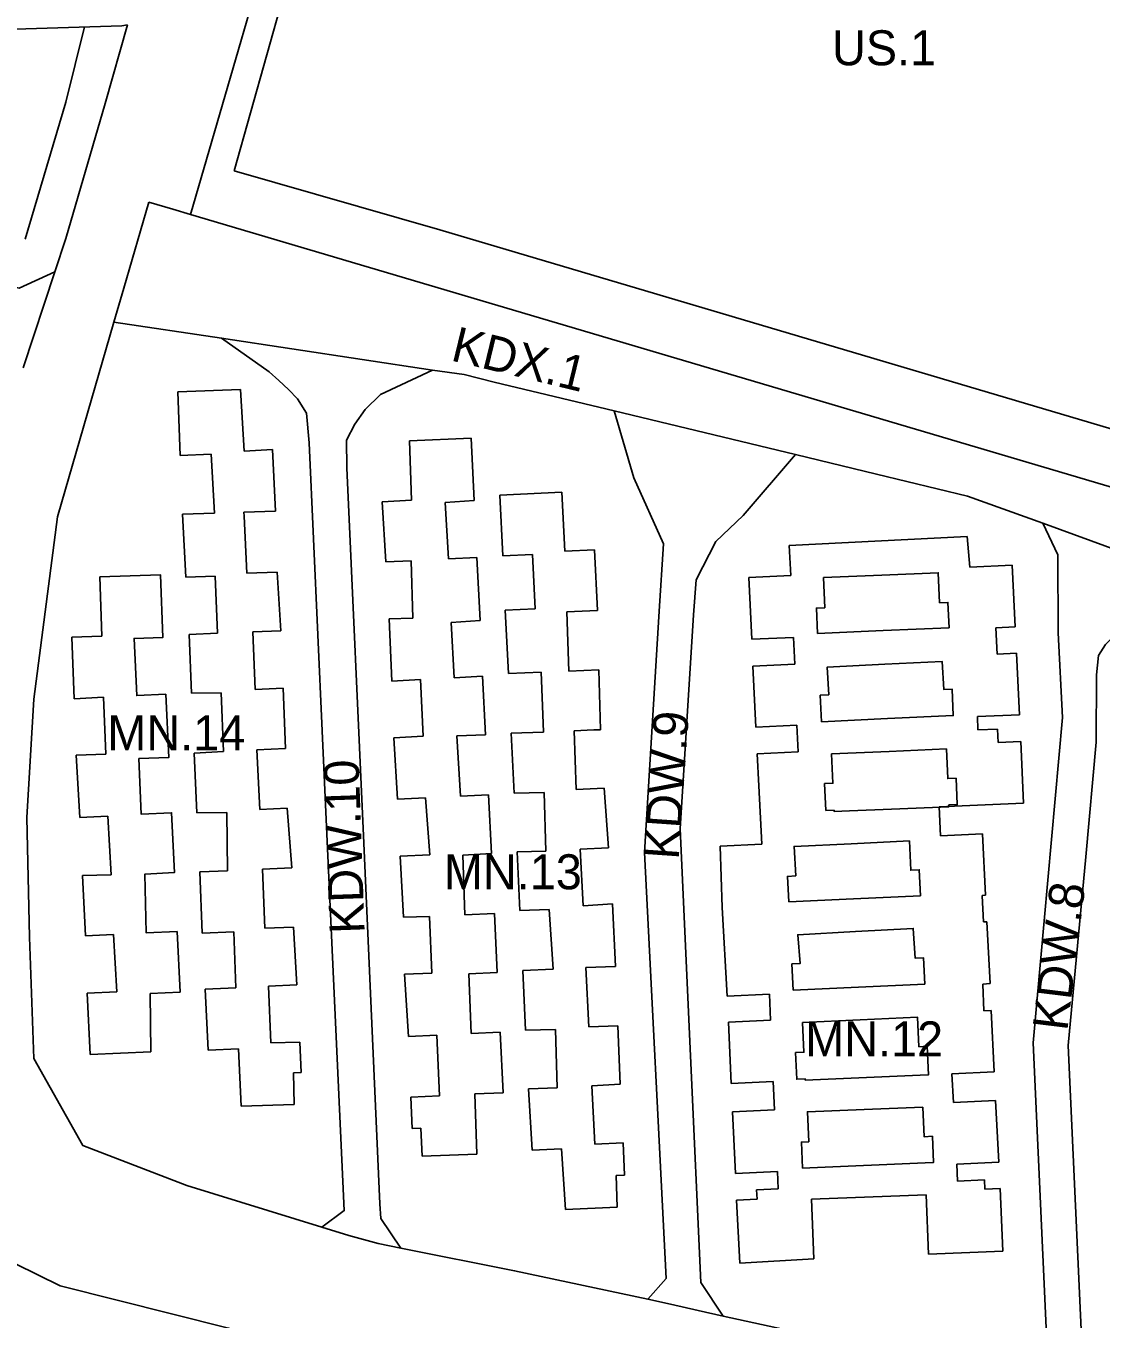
# Model space of a CAD drawing. Extents: x 7419601 to 7420547, y 5548907 to 5549873.
# Drawn here: x 7419879.6 to 7420033.1, y 5549211.8 to 5549396.6 of the extents above; entities that cross this region are included whole.
import ezdxf

# ---------------------------------------------------------------- set-up
doc = ezdxf.new("R2010")
doc.units = 0
for name, color, linetype in [('LIN_linie_rozgraniczajace', 7, 'Continuous'), ('LIN_nieprzekraczalna linia zabudowy', 7, 'Continuous'), ('LIN_obowiązująca linia zabudowy', 7, 'Continuous'), ('TXT_opisy_przeznaczen', 7, 'Continuous')]:
    doc.layers.add(name, color=color, linetype=linetype)

msp = doc.modelspace()

# ---------------------------------------------------------------- linework, layer by layer
at = {"layer": 'LIN_linie_rozgraniczajace'}
for p, q in [((7419879.24, 5549347.7), (7419883.76, 5549361.41)), ((7419907.57, 5549351.94), (7419937.7, 5549347.35)), ((7419963.61, 5549341.58), (7419989.53, 5549335.34)), ((7419925.75, 5549223.74), (7419929.9, 5549222.61)), ((7419971.65, 5549213.96), (7419975.63, 5549213.02))]:
    msp.add_line(p, q, dxfattribs=at)
for points in [[(7419903.11, 5549369.61), (7419918, 5549420.91), (7419915.74, 5549421.56), (7419928.75, 5549463.85), (7419929.6, 5549464.8), (7419930.22, 5549465.38), (7419937.48, 5549471), (7419944.7, 5549476.57)], [(7419866.43, 5549433.49), (7419858.54, 5549399.2), (7419868.91, 5549395.8), (7419893.34, 5549396.57), (7419894.15, 5549396.71)], [(7419894.15, 5549396.71), (7419890.95, 5549385.44), (7419885.34, 5549366.2), (7419883.76, 5549361.41)], [(7419892.2, 5549354.22), (7419893.6, 5549359.07), (7419897.16, 5549371.37)], [(7420059.02, 5549323.41), (7419903.11, 5549369.61), (7419900.61, 5549370.35), (7419897.16, 5549371.37)], [(7419831.86, 5549369.96), (7419850.13, 5549366.21), (7419853.2, 5549365.39), (7419878.68, 5549359.09), (7419883.76, 5549361.41)], [(7419892.2, 5549354.22), (7419884.16, 5549326.43), (7419880.75, 5549300.37), (7419879.74, 5549283.46), (7419880.12, 5549266.38), (7419880.75, 5549249.05)], [(7419907.57, 5549351.94), (7419892.2, 5549354.22)], [(7419921.86, 5549224.94), (7419925.08, 5549227.32), (7419922.56, 5549282.15), (7419920.05, 5549336.98), (7419919.71, 5549341.21), (7419918.41, 5549343.25), (7419917.14, 5549344.61), (7419915.75, 5549345.87), (7419914.37, 5549347.13), (7419907.57, 5549351.94)], [(7419933.15, 5549221.96), (7419930.28, 5549226.19), (7419930.18, 5549228.3), (7419927.86, 5549279.8), (7419925.44, 5549333.41), (7419925.42, 5549337.36), (7419926.58, 5549339.66), (7419928.07, 5549341.73), (7419930.27, 5549343.88), (7419937.7, 5549347.35)], [(7419937.7, 5549347.35), (7419942.19, 5549346.76), (7419946.5, 5549345.65), (7419963.61, 5549341.58)], [(7419963.61, 5549341.58), (7419966.41, 5549331.99), (7419970.66, 5549322.55)], [(7419989.53, 5549335.34), (7419982.04, 5549326.61), (7419978.13, 5549322.87), (7419975.32, 5549317.43), (7419974.93, 5549312.4), (7419973.06, 5549281.83), (7419974.53, 5549249.43), (7419976.01, 5549217.04), (7419979.2, 5549212.24)], [(7420024.81, 5549325.52), (7420014.06, 5549329.35), (7420001.08, 5549332.49), (7419989.53, 5549335.34)], [(7420022.45, 5549202.85), (7420025.54, 5549205.34), (7420023.43, 5549251.26), (7420025.54, 5549274.51), (7420027.65, 5549297.76), (7420027.03, 5549309.83), (7420026.97, 5549320.98), (7420024.81, 5549325.52)], [(7420024.81, 5549325.52), (7420036.14, 5549321.36), (7420048.72, 5549317.81)], [(7419970.66, 5549322.55), (7419970.06, 5549312.96), (7419969, 5549295.71), (7419967.93, 5549278.46), (7419971.04, 5549217.63), (7419968.42, 5549214.65)], [(7420048.72, 5549317.81), (7420035.84, 5549310.28), (7420033.75, 5549308.2), (7420032.79, 5549306.6), (7420032.47, 5549303.85), (7420032.44, 5549294.24), (7420030.96, 5549277.87), (7420028.44, 5549250.88), (7420029.48, 5549227.98), (7420030.53, 5549205.08), (7420033.23, 5549200.31)], [(7419880.75, 5549249.05), (7419887.77, 5549236.6), (7419902.62, 5549230.89), (7419921.86, 5549224.94), (7419925.75, 5549223.74)], [(7419971.65, 5549213.96), (7419968.42, 5549214.65), (7419949.39, 5549218.71), (7419933.15, 5549221.96), (7419929.9, 5549222.61)], [(7419932.6, 5549204.46), (7419924.26, 5549206.56), (7419908.56, 5549210.52), (7419884.53, 5549216.57), (7419878.14, 5549219.72), (7419875.61, 5549220.97)], [(7419975.63, 5549213.02), (7419979.2, 5549212.24), (7420001.06, 5549207.47), (7420022.45, 5549202.85), (7420026.14, 5549202.05)]]:
    msp.add_lwpolyline(points, dxfattribs=at)
at = {"layer": 'LIN_nieprzekraczalna linia zabudowy'}
for p, q in [((7419932.96, 5549459.71), (7419909.37, 5549375.84)), ((7419909.37, 5549375.84), (7419938.72, 5549367.4))]:
    msp.add_line(p, q, dxfattribs=at)
for points in [[(7419879.51, 5549366.06), (7419885.32, 5549385.64), (7419887.98, 5549396.4)], [(7419938.72, 5549367.4), (7420051.91, 5549333.86)]]:
    msp.add_lwpolyline(points, dxfattribs=at)
at = {"layer": 'LIN_obowiązująca linia zabudowy'}
for p, q in [((7419910.25, 5549344.62), (7419901.3, 5549344.25)), ((7419901.3, 5549344.25), (7419901.67, 5549335.16)), ((7419910.78, 5549335.81), (7419910.25, 5549344.62)), ((7419943.21, 5549337.65), (7419934.38, 5549337.29)), ((7419934.38, 5549337.29), (7419934.68, 5549328.81)), ((7419943.62, 5549328.74), (7419943.21, 5549337.65)), ((7419901.67, 5549335.16), (7419906.09, 5549335.35)), ((7419906.09, 5549335.35), (7419906.54, 5549326.92)), ((7419914.83, 5549336.02), (7419910.78, 5549335.81)), ((7419915.26, 5549327.23), (7419914.83, 5549336.02)), ((7419956.16, 5549329.92), (7419947.28, 5549329.49)), ((7419947.28, 5549329.49), (7419947.7, 5549320.83)), ((7419956.57, 5549321.49), (7419956.16, 5549329.92)), ((7419910.74, 5549327.06), (7419915.26, 5549327.23)), ((7419910.77, 5549326.52), (7419910.74, 5549327.06)), ((7419934.68, 5549328.81), (7419930.49, 5549328.56)), ((7419930.49, 5549328.56), (7419931.01, 5549319.97)), ((7419939.5, 5549328.47), (7419943.62, 5549328.74)), ((7419939.94, 5549320.41), (7419939.5, 5549328.47)), ((7419906.54, 5549326.92), (7419902, 5549326.79)), ((7419902, 5549326.79), (7419902.48, 5549317.78)), ((7419911.19, 5549318.39), (7419910.77, 5549326.52)), ((7420014.04, 5549323.59), (7419988.6, 5549322.34)), ((7420014.42, 5549319.21), (7420014.04, 5549323.59)), ((7419960.82, 5549321.7), (7419956.57, 5549321.49)), ((7419961.22, 5549313.05), (7419960.82, 5549321.7)), ((7419988.6, 5549322.34), (7419988.85, 5549318.03)), ((7419931.01, 5549319.97), (7419934.63, 5549320.15)), ((7419934.63, 5549320.15), (7419934.89, 5549311.96)), ((7419944.02, 5549320.62), (7419939.94, 5549320.41)), ((7419944.48, 5549311.59), (7419944.02, 5549320.62)), ((7419947.7, 5549320.83), (7419951.98, 5549321.04)), ((7419951.98, 5549321.04), (7419952.36, 5549313.26)), ((7419890.18, 5549317.83), (7419890.45, 5549309.37)), ((7419902.48, 5549317.78), (7419906.65, 5549317.93)), ((7419906.65, 5549317.93), (7419906.99, 5549309.78)), ((7419915.48, 5549318.53), (7419911.19, 5549318.39)), ((7419916.03, 5549310.14), (7419915.48, 5549318.53)), ((7419988.85, 5549318.03), (7419982.83, 5549317.74)), ((7420020.43, 5549319.5), (7420014.42, 5549319.21)), ((7420020.86, 5549310.71), (7420020.43, 5549319.5)), ((7419982.83, 5549317.74), (7419983.26, 5549308.93)), ((7419952.36, 5549313.26), (7419948.07, 5549313.07)), ((7419948.07, 5549313.07), (7419948.51, 5549304.05)), ((7419956.86, 5549312.84), (7419961.22, 5549313.05)), ((7419957.13, 5549304.37), (7419956.86, 5549312.84)), ((7419934.89, 5549311.96), (7419931.48, 5549311.83)), ((7419931.48, 5549311.83), (7419931.87, 5549302.95)), ((7419940.34, 5549311.33), (7419944.48, 5549311.59)), ((7419940.76, 5549303.44), (7419940.34, 5549311.33)), ((7420018.12, 5549310.58), (7420020.86, 5549310.71)), ((7420018.31, 5549306.82), (7420018.12, 5549310.58)), ((7419890.45, 5549309.37), (7419886.17, 5549309.25)), ((7419886.17, 5549309.25), (7419886.54, 5549300.44)), ((7419906.99, 5549309.78), (7419902.92, 5549309.62)), ((7419902.92, 5549309.62), (7419903.26, 5549301.23)), ((7419912.01, 5549309.98), (7419916.03, 5549310.14)), ((7419912.34, 5549301.77), (7419912.01, 5549309.98)), ((7419983.26, 5549308.93), (7419989.21, 5549309.2)), ((7419989.21, 5549309.2), (7419989.39, 5549305.38)), ((7420021.05, 5549306.96), (7420018.31, 5549306.82)), ((7420021.5, 5549298.14), (7420021.05, 5549306.96)), ((7419989.39, 5549305.38), (7419983.43, 5549305.1)), ((7419983.43, 5549305.1), (7419983.84, 5549296.36)), ((7419931.87, 5549302.95), (7419935.97, 5549303.18)), ((7419935.97, 5549303.18), (7419936.36, 5549295.1)), ((7419944.84, 5549303.67), (7419940.76, 5549303.44)), ((7419945.26, 5549295.26), (7419944.84, 5549303.67)), ((7419948.51, 5549304.05), (7419953.21, 5549304.23)), ((7419953.21, 5549304.23), (7419953.4, 5549299.44)), ((7419961.43, 5549304.55), (7419957.13, 5549304.37)), ((7419961.65, 5549296.01), (7419961.43, 5549304.55)), ((7419903.26, 5549301.23), (7419907.49, 5549301.28)), ((7419907.49, 5549301.28), (7419907.85, 5549292.88)), ((7419916.37, 5549301.93), (7419912.34, 5549301.77)), ((7419916.7, 5549293.31), (7419916.37, 5549301.93)), ((7419886.54, 5549300.44), (7419890.69, 5549300.64)), ((7419890.69, 5549300.64), (7419891.05, 5549292.5)), ((7419953.4, 5549299.44), (7419953.55, 5549295.66)), ((7420015.5, 5549297.88), (7420021.5, 5549298.14)), ((7420015.54, 5549295.98), (7420015.5, 5549297.88)), ((7419953.55, 5549295.66), (7419948.93, 5549295.5)), ((7419957.91, 5549295.86), (7419960.72, 5549295.97)), ((7419958.2, 5549287.48), (7419957.91, 5549295.86)), ((7419960.72, 5549295.97), (7419961.65, 5549296.01)), ((7419983.84, 5549296.36), (7419989.68, 5549296.67)), ((7419989.68, 5549296.67), (7419989.88, 5549292.84)), ((7420018.33, 5549296.1), (7420015.54, 5549295.98)), ((7420018.42, 5549294.2), (7420018.33, 5549296.1)), ((7419936.36, 5549295.1), (7419932.16, 5549294.86)), ((7419932.16, 5549294.86), (7419932.68, 5549286.08)), ((7419941.15, 5549295.11), (7419945.26, 5549295.26)), ((7419941.7, 5549286.52), (7419941.15, 5549295.11)), ((7419948.93, 5549295.5), (7419949.35, 5549286.95)), ((7420021.66, 5549294.34), (7420018.42, 5549294.2)), ((7420022.05, 5549285.51), (7420021.66, 5549294.34)), ((7419891.05, 5549292.5), (7419886.82, 5549292.38)), ((7419886.82, 5549292.38), (7419887.32, 5549283.45)), ((7419907.85, 5549292.88), (7419903.66, 5549292.67)), ((7419903.66, 5549292.67), (7419904.05, 5549284.12)), ((7419912.62, 5549293.12), (7419916.7, 5549293.31)), ((7419913.02, 5549284.62), (7419912.62, 5549293.12)), ((7419989.88, 5549292.84), (7419984.04, 5549292.54)), ((7419984.04, 5549292.54), (7419984.28, 5549287.97)), ((7419945.68, 5549286.72), (7419941.7, 5549286.52)), ((7419946.09, 5549278.33), (7419945.68, 5549286.72)), ((7419949.35, 5549286.95), (7419953.64, 5549287.05)), ((7419953.64, 5549287.05), (7419953.84, 5549278.65)), ((7419962.2, 5549287.67), (7419958.2, 5549287.48)), ((7419962.8, 5549279.14), (7419962.2, 5549287.67)), ((7419984.28, 5549287.97), (7419984.72, 5549279.67)), ((7419916.94, 5549284.81), (7419913.02, 5549284.62)), ((7419917.6, 5549276.27), (7419916.94, 5549284.81)), ((7419932.68, 5549286.08), (7419936.69, 5549286.28)), ((7419936.69, 5549286.28), (7419937.28, 5549278.11)), ((7420010.01, 5549284.97), (7420022.05, 5549285.51)), ((7420010.2, 5549280.86), (7420010.01, 5549284.97)), ((7419887.32, 5549283.45), (7419891.33, 5549283.66)), ((7419891.33, 5549283.66), (7419891.82, 5549275.29)), ((7419904.05, 5549284.12), (7419908.31, 5549284.18)), ((7419908.31, 5549284.18), (7419908.43, 5549275.85)), ((7420016.22, 5549281.13), (7420010.2, 5549280.86)), ((7420016.62, 5549272.35), (7420016.22, 5549281.13)), ((7419958.76, 5549278.96), (7419962.8, 5549279.14)), ((7419984.72, 5549279.67), (7419978.73, 5549279.35)), ((7419978.73, 5549279.35), (7419979.04, 5549270.63)), ((7419937.28, 5549278.11), (7419933.06, 5549277.94)), ((7419933.06, 5549277.94), (7419933.54, 5549269.23)), ((7419942.02, 5549278.09), (7419946.09, 5549278.33)), ((7419942.29, 5549269.56), (7419942.02, 5549278.09)), ((7419953.84, 5549278.65), (7419949.75, 5549278.56)), ((7419949.75, 5549278.56), (7419950.16, 5549270.18)), ((7419959.19, 5549270.84), (7419958.76, 5549278.96)), ((7419908.43, 5549275.85), (7419904.44, 5549275.72)), ((7419904.44, 5549275.72), (7419904.8, 5549266.95)), ((7419913.42, 5549276.09), (7419917.6, 5549276.27)), ((7419913.75, 5549267.66), (7419913.42, 5549276.09)), ((7419891.82, 5549275.29), (7419887.7, 5549275.16)), ((7419887.7, 5549275.16), (7419888.14, 5549266.57)), ((7420016.14, 5549272.34), (7420016.62, 5549272.35)), ((7420016.14, 5549272.29), (7420016.14, 5549272.34)), ((7420016.34, 5549268.55), (7420016.14, 5549272.29)), ((7419946.51, 5549269.77), (7419942.29, 5549269.56)), ((7419946.92, 5549261.34), (7419946.51, 5549269.77)), ((7419950.16, 5549270.18), (7419954.32, 5549270.33)), ((7419954.32, 5549270.33), (7419954.92, 5549261.82)), ((7419963.36, 5549271.12), (7419959.19, 5549270.84)), ((7419963.81, 5549262.2), (7419963.36, 5549271.12)), ((7419979.04, 5549270.63), (7419979.75, 5549257.93)), ((7419933.54, 5549269.23), (7419937.24, 5549269.32)), ((7419937.24, 5549269.32), (7419937.57, 5549261.24)), ((7420016.82, 5549268.58), (7420016.34, 5549268.55)), ((7420017.29, 5549259.74), (7420016.82, 5549268.58)), ((7419888.14, 5549266.57), (7419892.15, 5549266.76)), ((7419892.15, 5549266.76), (7419892.63, 5549258.56)), ((7419901.65, 5549258.53), (7419901.24, 5549267.2)), ((7419904.8, 5549266.95), (7419909.31, 5549267.12)), ((7419909.31, 5549267.12), (7419909.61, 5549259.11)), ((7419917.81, 5549267.81), (7419913.75, 5549267.66)), ((7419918.32, 5549259.58), (7419917.81, 5549267.81)), ((7419937.57, 5549261.24), (7419933.67, 5549261.08)), ((7419933.67, 5549261.08), (7419934.24, 5549252.16)), ((7419942.86, 5549261.14), (7419946.92, 5549261.34)), ((7419943.19, 5549252.61), (7419942.86, 5549261.14)), ((7419954.92, 5549261.82), (7419950.57, 5549261.63)), ((7419950.57, 5549261.63), (7419950.98, 5549253.08)), ((7419959.59, 5549262.02), (7419963.81, 5549262.2)), ((7419960.02, 5549253.55), (7419959.59, 5549262.02)), ((7419909.61, 5549259.11), (7419905.22, 5549258.93)), ((7419905.22, 5549258.93), (7419905.63, 5549250.25)), ((7419914.25, 5549259.38), (7419918.32, 5549259.58)), ((7419914.61, 5549251.26), (7419914.25, 5549259.38)), ((7420016.24, 5549259.68), (7420017.29, 5549259.74)), ((7420016.42, 5549255.87), (7420016.24, 5549259.68)), ((7419892.63, 5549258.56), (7419888.37, 5549258.35)), ((7419888.37, 5549258.35), (7419888.8, 5549249.6)), ((7419897.37, 5549258.31), (7419901.65, 5549258.53)), ((7419897.47, 5549250), (7419897.37, 5549258.31)), ((7419979.75, 5549257.93), (7419985.78, 5549258.21)), ((7419985.78, 5549258.21), (7419985.95, 5549254.51)), ((7420017.46, 5549255.91), (7420016.42, 5549255.87)), ((7420017.86, 5549247.14), (7420017.46, 5549255.91)), ((7419950.98, 5549253.08), (7419955.23, 5549253.2)), ((7419955.23, 5549253.2), (7419955.47, 5549244.84)), ((7419964.16, 5549253.71), (7419960.02, 5549253.55)), ((7419964.46, 5549245.35), (7419964.16, 5549253.71)), ((7419985.95, 5549254.51), (7419979.92, 5549254.23)), ((7419979.92, 5549254.23), (7419980.32, 5549245.46)), ((7419918.74, 5549251.39), (7419914.61, 5549251.26)), ((7419918.92, 5549247.04), (7419918.74, 5549251.39)), ((7419934.24, 5549252.16), (7419938.29, 5549252.36)), ((7419938.29, 5549252.36), (7419938.68, 5549243.7)), ((7419947.35, 5549252.82), (7419943.19, 5549252.61)), ((7419947.78, 5549244.15), (7419947.35, 5549252.82)), ((7419888.8, 5549249.6), (7419897.47, 5549250)), ((7419905.63, 5549250.25), (7419909.99, 5549250.4)), ((7419909.99, 5549250.4), (7419910.36, 5549242.22)), ((7419917.84, 5549247), (7419918.92, 5549247.04)), ((7419917.95, 5549242.46), (7419917.84, 5549247)), ((7420011.85, 5549246.87), (7420017.86, 5549247.14)), ((7420012.06, 5549242.73), (7420011.85, 5549246.87)), ((7419943.74, 5549243.98), (7419947.78, 5549244.15)), ((7419944.01, 5549235.38), (7419943.74, 5549243.98)), ((7419955.47, 5549244.84), (7419951.39, 5549244.69)), ((7419951.39, 5549244.69), (7419951.91, 5549235.96)), ((7419960.44, 5549245.15), (7419964.46, 5549245.35)), ((7419960.86, 5549236.8), (7419960.44, 5549245.15)), ((7419980.32, 5549245.46), (7419986.31, 5549245.73)), ((7419986.31, 5549245.73), (7419986.49, 5549241.7)), ((7419910.36, 5549242.22), (7419917.95, 5549242.46)), ((7419938.68, 5549243.7), (7419934.6, 5549243.53)), ((7419934.6, 5549243.53), (7419934.79, 5549239.02)), ((7420018.07, 5549243.05), (7420012.06, 5549242.73)), ((7420018.54, 5549234.21), (7420018.07, 5549243.05)), ((7419986.49, 5549241.7), (7419980.51, 5549241.43)), ((7419980.51, 5549241.43), (7419980.92, 5549232.61)), ((7419934.79, 5549239.02), (7419936.02, 5549239.07)), ((7419936.02, 5549239.07), (7419936.19, 5549235.07)), ((7419964.89, 5549237), (7419960.86, 5549236.8)), ((7419965.08, 5549232.39), (7419964.89, 5549237)), ((7419936.19, 5549235.07), (7419944.01, 5549235.38)), ((7419951.91, 5549235.96), (7419956.08, 5549236.13)), ((7419956.08, 5549236.13), (7419956.65, 5549227.46)), ((7419980.92, 5549232.61), (7419986.96, 5549232.9)), ((7419986.96, 5549232.9), (7419987.05, 5549230.41)), ((7420012.54, 5549233.93), (7420018.54, 5549234.21)), ((7420012.66, 5549231.52), (7420012.54, 5549233.93)), ((7419963.88, 5549232.34), (7419965.08, 5549232.39)), ((7419964.06, 5549227.79), (7419963.88, 5549232.34)), ((7420016.49, 5549231.7), (7420012.66, 5549231.52)), ((7420016.55, 5549230.38), (7420016.49, 5549231.7)), ((7419987.05, 5549230.41), (7419983.96, 5549230.26)), ((7419983.96, 5549230.26), (7419984.02, 5549228.95)), ((7419991.78, 5549228.92), (7420008.17, 5549229.58)), ((7420008.17, 5549229.58), (7420008.51, 5549221.08)), ((7420018.71, 5549230.48), (7420016.55, 5549230.38)), ((7420019.13, 5549221.51), (7420018.71, 5549230.48)), ((7419956.65, 5549227.46), (7419964.06, 5549227.79)), ((7419984.02, 5549228.95), (7419981.1, 5549228.81)), ((7419981.1, 5549228.81), (7419981.54, 5549219.81)), ((7419992.12, 5549220.42), (7419991.78, 5549228.92)), ((7419981.54, 5549219.81), (7419992.12, 5549220.42)), ((7420008.51, 5549221.08), (7420019.13, 5549221.51))]:
    msp.add_line(p, q, dxfattribs=at)
msp.add_lwpolyline([(7419901.24, 5549267.2), (7419896.82, 5549266.97), (7419896.61, 5549275.39), (7419900.83, 5549275.59), (7419900.42, 5549284.14), (7419896.1, 5549283.93), (7419895.75, 5549291.88), (7419900.05, 5549292.05), (7419899.6, 5549301.08), (7419895.46, 5549300.87), (7419895.07, 5549309.04), (7419899.2, 5549309.19), (7419898.82, 5549318.14), (7419890.18, 5549317.83)], dxfattribs=at)
for points in [[(7419992.65, 5549309.76), (7419992.5, 5549313.38), (7419993.69, 5549313.43), (7419993.51, 5549317.73), (7420001.82, 5549318.09), (7420009.89, 5549318.44), (7420010.08, 5549314.14), (7420011.28, 5549314.19), (7420011.43, 5549310.57), (7420002.04, 5549310.17)], [(7419993.23, 5549297.15), (7419993.05, 5549300.94), (7419994.25, 5549301), (7419994.05, 5549304.95), (7420002.28, 5549305.35), (7420010.47, 5549305.75), (7420010.67, 5549301.76), (7420011.87, 5549301.82), (7420012.04, 5549298.02), (7420002.65, 5549297.6)], [(7419993.82, 5549284.45), (7419993.65, 5549288.3), (7419994.85, 5549288.35), (7419994.67, 5549292.54), (7420002.86, 5549292.9), (7420011.05, 5549293.26), (7420011.24, 5549289.02), (7420012.44, 5549289.07), (7420012.6, 5549285.32), (7420011.4, 5549285.27), (7420011.41, 5549285.01), (7420003.22, 5549284.66), (7419997.22, 5549284.4), (7419995.03, 5549284.3), (7419995.02, 5549284.5)], [(7419988.57, 5549271.4), (7419988.35, 5549275.06), (7419989.55, 5549275.14), (7419989.3, 5549279.33), (7419997.44, 5549279.71), (7420005.77, 5549280.11), (7420005.97, 5549275.93), (7420007.17, 5549275.99), (7420007.34, 5549272.29), (7419997.81, 5549271.84)], [(7419989.17, 5549258.79), (7419988.99, 5549262.55), (7419990.19, 5549262.61), (7419989.83, 5549266.72), (7419998.07, 5549267.18), (7420006.31, 5549267.63), (7420006.57, 5549263.38), (7420007.77, 5549263.44), (7420007.95, 5549259.67), (7419998.51, 5549259.22)], [(7419990.9, 5549245.93), (7419990.89, 5549246.13), (7419989.69, 5549246.08), (7419989.52, 5549249.88), (7419990.72, 5549249.93), (7419990.53, 5549254.18), (7419998.72, 5549254.54), (7420006.93, 5549254.92), (7420007.12, 5549250.72), (7420008.32, 5549250.78), (7420008.5, 5549246.72), (7420007.3, 5549246.67)], [(7419991.57, 5549233.43), (7419990.52, 5549233.38), (7419990.36, 5549237.1), (7419991.41, 5549237.15), (7419991.22, 5549241.42), (7419999.32, 5549241.74), (7420007.67, 5549242.07), (7420007.86, 5549237.87), (7420009.05, 5549237.93), (7420009.22, 5549234.2), (7420008.02, 5549234.15)]]:
    msp.add_lwpolyline(points, close=True, dxfattribs=at)

# ---------------------------------------------------------------- texts
at = {"layer": 'TXT_opisy_przeznaczen'}
for s, p in [('US.1', (7419994.72, 5549390.92)), ('MN.14', (7419891.25, 5549293.06)), ('MN.13', (7419939.31, 5549273.21)), ('MN.12', (7419990.89, 5549249.34))]:
    msp.add_text(s, height=5, dxfattribs=at).set_placement(p)
for s, rotation, p in [('KDX.1', 346.3598, (7419940.13, 5549348.79)), ('KDW.9', 86, (7419972.82, 5549277.37)), ('KDW.10', 92, (7419928, 5549266.94)), ('KDW.8', 83, (7420028.31, 5549252.87))]:
    msp.add_text(s, height=5, rotation=rotation, dxfattribs=at).set_placement(p)

doc.saveas('drawing.dxf')
